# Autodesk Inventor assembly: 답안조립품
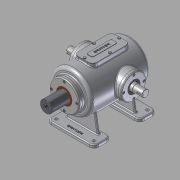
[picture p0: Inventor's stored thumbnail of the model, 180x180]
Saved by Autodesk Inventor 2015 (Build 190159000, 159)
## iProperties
Created: 2016-02
Part Number: 답안조립품
Document SubType Name: Assembly
Designer: Administrator
Mass: 8191.33 g
Surface Area: 4241.84 cm^2
Volume: 1855.51 cm^3
Density: 4.41461 g/cm^3
Author: Administrator
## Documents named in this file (15)
- C:\Users\Administrator\Desktop\360220V1006\답안조립품.iam
- C:\Users\Administrator\Desktop\360220V1006\본체.ipt
- C:\Users\Administrator\Desktop\360220V1006\베어링 6205.ipt
- 베어링 6205.ipt
- C:\Users\Administrator\Desktop\360220V1006\축 커버.ipt
- C:\Users\Administrator\Desktop\360220V1006\오일실.ipt
- 오일실.ipt
- C:\Users\Administrator\Desktop\360220V1006\볼트 M4x0.7.ipt
- C:\Users\Administrator\Desktop\360220V1006\상부커버.ipt
- C:\Users\Administrator\Desktop\360220V1006\육각머리볼트 M4.ipt
- C:\Users\Administrator\Desktop\360220V1006\편심축.ipt
- C:\Users\Administrator\Desktop\360220V1006\슬라이드 커버.ipt
- C:\Users\Administrator\Desktop\360220V1006\부시.ipt
- C:\Users\Administrator\Desktop\360220V1006\슬라이드.ipt
- C:\Users\Administrator\Desktop\360220V1006\가변스프링.ipt
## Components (13 placed, 2 different names)
1. 가변스프링:1
2. M4x0.7:1
3. M4x0.7:2
4. M4x0.7:3
5. M4x0.7:4
6. M4x0.7:5
7. M4x0.7:6
8. M4x0.7:7
9. M4x0.7:8
10. M4x0.7:9
11. M4x0.7:10
12. M4x0.7:11
13. M4x0.7:12
